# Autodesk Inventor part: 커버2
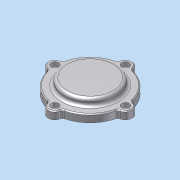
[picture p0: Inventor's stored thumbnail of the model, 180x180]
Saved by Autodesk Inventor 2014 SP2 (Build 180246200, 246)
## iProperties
Company: 한국ATC센터
Created: 2015-03
Part Number: 커버2
Document SubType Name: Modeling
Designer: KYOUNG IL JANG
Density: 1 g/cm^3
Material: 일반
Appearance: 기본값
Author: KYOUNG IL JANG
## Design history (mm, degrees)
sketch "스케치1"
  geometry: C1 r 1.621 at (0, 6.75) reference; C2 r 1.621 at (-37, -30.25) reference; C3 r 1.621 at (0, -67.25) reference; C4 r 1.621 at (37, -30.25) reference; C5 r 10 at (0, -30.25) reference; C6 r 12 at (0, -30.25); C7 r 24.5 at (0, -30.25) reference; A1 r 3 centre (-38.77, -20.408) between (-38.239, -23.361) and (-35.862, -21.146) reference; A2 r 7 centre (-37, -30.25) between (-38.239, -23.361) and (-38.239, -37.139) reference; A3 r 3 centre (-38.77, -40.092) between (-35.862, -39.354) and (-38.239, -37.139) reference; A4 r 37 centre (0, -30.25) between (-35.862, -39.354) and (-9.104, -66.113) reference; A5 r 3 centre (-9.842, -69.02) between (-6.889, -68.489) and (-9.104, -66.113) reference; A6 r 7 centre (0, -67.25) between (-6.889, -68.489) and (6.889, -68.489) reference; A7 r 3 centre (9.842, -69.02) between (9.104, -66.112) and (6.889, -68.489) reference; A8 r 37 centre (0, -30.25) between (9.104, -66.112) and (35.863, -39.354) reference; A9 r 3 centre (38.77, -40.092) between (38.239, -37.139) and (35.863, -39.354) reference; A10 r 7 centre (37, -30.25) between (38.239, -37.139) and (38.239, -23.361) reference; A11 r 3 centre (38.77, -20.408) between (35.863, -21.146) and (38.239, -23.361) reference; A12 r 37 centre (0, -30.25) between (35.863, -21.146) and (9.104, 5.612) reference; A13 r 3 centre (9.842, 8.52) between (6.889, 7.989) and (9.104, 5.612) reference; A14 r 7 centre (0, 6.75) between (6.889, 7.989) and (-6.889, 7.989) reference; A15 r 3 centre (-9.842, 8.52) between (-9.104, 5.612) and (-6.889, 7.989) reference; A16 r 37 centre (0, -30.25) between (-9.104, 5.612) and (-35.862, -21.146) reference; 1 further point
  constraints: 1 centre point, 1 coincident
  dimensions: "d2" = 2 radial gap between concentric circles of C6 C5
extrude "돌출1" new body sketch "스케치1" distance "d0" = 8; taper "d1" = 0 deg
sketch "스케치2"
  geometry: C1 r 23.5 at (0, -30.25) reference; C2 r 12 at (0, -30.25) reference; 1 further point
extrude "돌출2" join sketch "스케치2" distance "d4" = 5; taper "d5" = 0 deg
sketch "스케치3"
  geometry: C1 r 23.5 at (0, 0) reference; C2 r 20.5 at (0, 0); 1 further point
  constraints: 1 centre point
  dimensions: "d6" = 3 radial gap between concentric circles of C2 C1
node "작업 평면1"
extrude "돌출3" join sketch "스케치3" stored distance "d7" = 5; taper "d8" = 0 deg
fillet "모깎기1" dims "d9" = 3
sketch "스케치4"
  geometry: C1 r 12 at (0, -30.25) reference; C2 r 27 at (0, -30.25); 1 further point
  constraints: 1 centre point
  dimensions: "d10" = 15 radial gap between concentric circles of C1 C2
extrude "돌출4" join sketch "스케치4" distance "d11" = 7; taper "d12" = 0 deg
fillet "모깎기2" dims "d13" = 3
chamfer "모따기1" distance "d14" = 1; stored, may be unused: second distance "d15" = 2, angle "d16" = 45 deg
node "작업점1"
  node "작업축1"
chamfer "모따기2" distance "d24" = 1; stored, may be unused: second distance "d25" = 2, angle "d26" = 45 deg
hole "구멍6" diameter "d43" = 4.5; stored, may be unused: countersink angle "d47" = 90 deg, drill point angle "d49" = 118 deg; dims "d41" = 10, "d42" = 10, "d44" = 6, "d45" = 8, "d46" = 4.4, "d48" = 8
fillet "모깎기4" dims "d60" = 3
node "솔리드1"
pattern_circular "원형 패턴1" dims angle "d51" = 360 deg
node "참조1"
node "참조2"
